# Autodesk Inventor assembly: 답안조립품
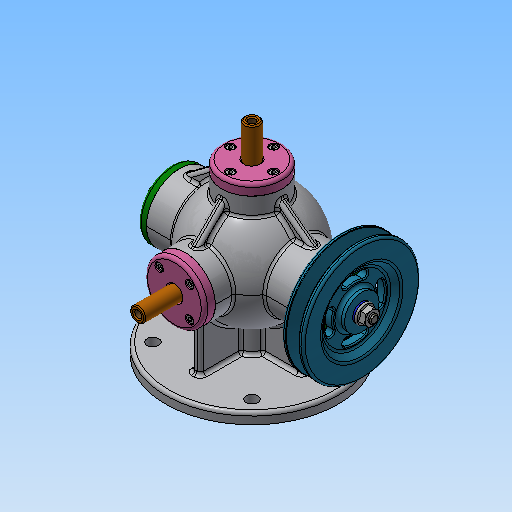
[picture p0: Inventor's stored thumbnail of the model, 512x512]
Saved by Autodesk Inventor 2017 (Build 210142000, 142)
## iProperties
Part Number: 답안조립품
Material: 일반
Document SubType Name: Assembly
Designer: MRC
Mass: 3733.58 g
Surface Area: 2584.17 cm^2
Volume: 938.795 cm^3
Density: 3.97699 g/cm^3
Author: MRC
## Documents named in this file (17)
- C:\Users\MRC\Desktop\620909V1004_\620909V1004\답안조립품.iam
- C:\Users\MRC\Desktop\620909V1004_\620909V1004\본체.ipt
- C:\Users\MRC\Desktop\620909V1004_\620909V1004\V-벨트풀리.ipt
- C:\Users\MRC\Desktop\620909V1004_\620909V1004\너트-M8x1.ipt
- C:\Users\MRC\Desktop\620909V1004_\620909V1004\뒤커버.ipt
- C:\Users\MRC\Desktop\620909V1004_\620909V1004\베어링- 6202.ipt
- C:\Users\MRC\Desktop\620909V1004_\620909V1004\본체커버.ipt
- C:\Users\MRC\Desktop\620909V1004_\620909V1004\볼트 M4x0.7.ipt
- C:\Users\MRC\Desktop\620909V1004_\620909V1004\슬라이드 커버.ipt
- C:\Users\MRC\Desktop\620909V1004_\620909V1004\슬라이드.ipt
- C:\Users\MRC\Desktop\620909V1004_\620909V1004\앞커버.ipt
- C:\Users\MRC\Desktop\620909V1004_\620909V1004\오일실.ipt
- C:\Users\MRC\Desktop\620909V1004_\620909V1004\와셔 8x17.ipt
- C:\Users\MRC\Desktop\620909V1004_\620909V1004\축.ipt
- C:\Users\MRC\Desktop\620909V1004_\620909V1004\키-4x4.ipt
- C:\Users\MRC\Desktop\620909V1004_\620909V1004\가변스프링1.ipt
- C:\Users\MRC\Desktop\620909V1004_\620909V1004\가변스프링2.ipt
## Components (20 placed, 4 different names)
1. V-벨트풀리:1
2. M4x0.7x12:1
3. M4x0.7x12:2
4. M4x0.7x12:3
5. M4x0.7x12:4
6. M4x0.7x12:5
7. M4x0.7x12:6
8. M4x0.7x12:7
9. M4x0.7x12:8
10. M4x0.7x12:9
11. M4x0.7x12:10
12. M4x0.7x12:11
13. M4x0.7x12:12
14. M4x0.7x12:13
15. M4x0.7x12:14
16. M4x0.7x12:15
17. M4x0.7x12:16
18. M4x0.7x12:17
19. 가변스프링1:1
20. 가변스프링2:1
